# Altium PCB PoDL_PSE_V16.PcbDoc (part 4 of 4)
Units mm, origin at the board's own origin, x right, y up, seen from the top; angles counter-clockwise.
Board outline 155 x 86.5 mm, 4 copper layers (Top Layer, Signal Layer 2, Signal Layer 3, Bottom Layer), stack 1.586 mm thick; 431 components, 281 nets, 1286 pads, 864 vias.
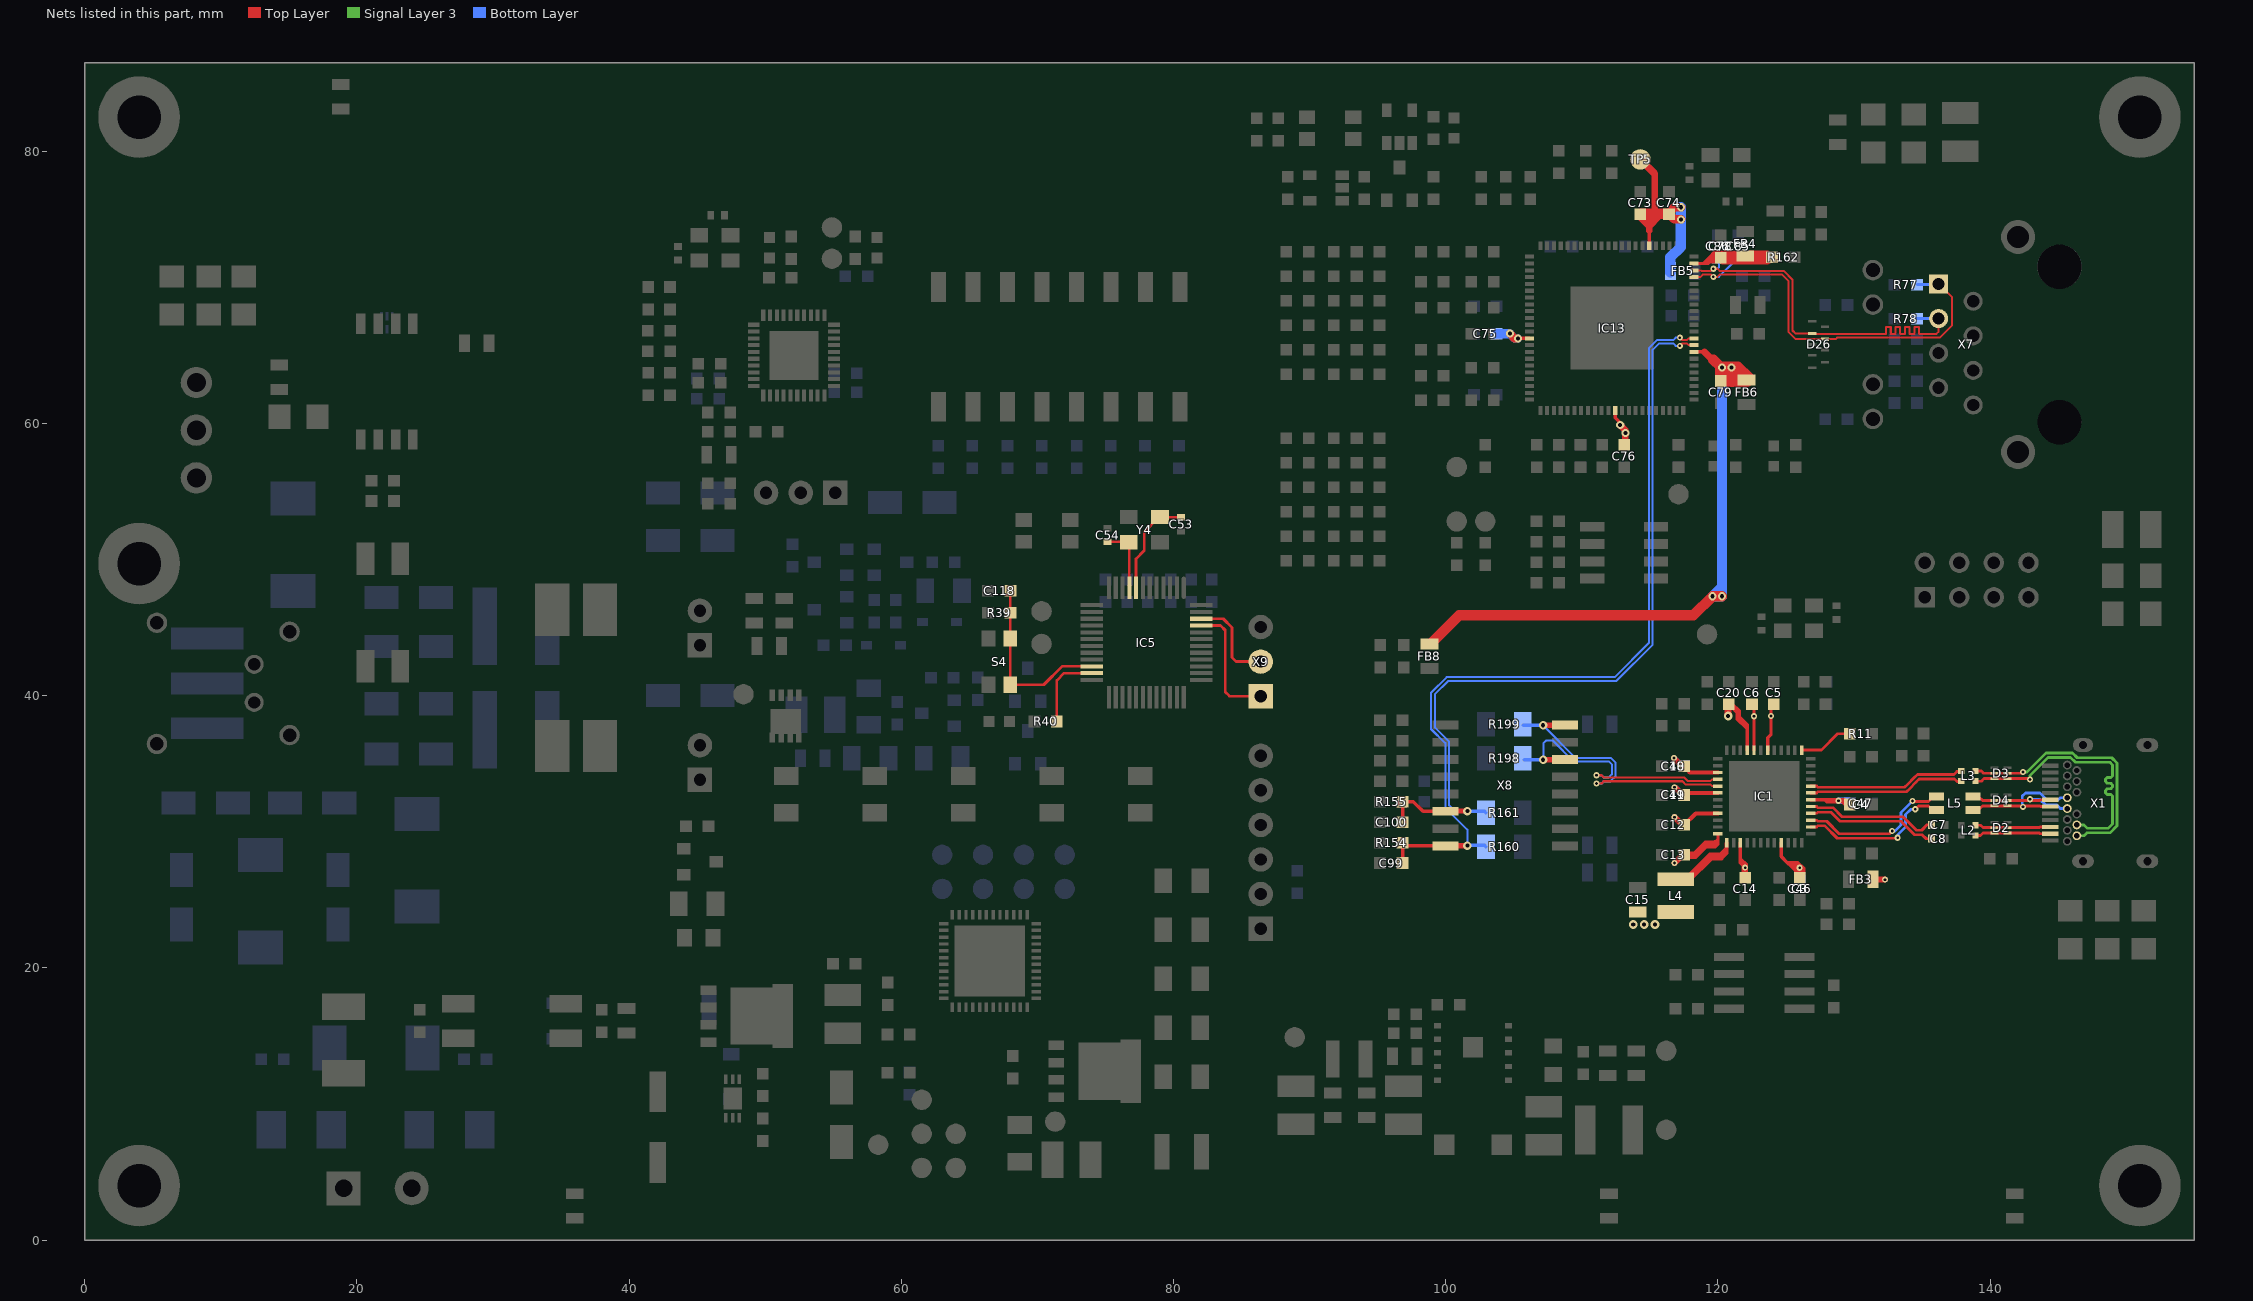
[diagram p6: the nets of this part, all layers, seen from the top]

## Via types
v1: diameter 0.6, hole 0.3, Top Layer to Bottom Layer, tented both sides, 494 vias
v2: diameter 0.45, hole 0.2, Top Layer to Bottom Layer, tented both sides, 173 vias
v3: diameter 0.635, hole 0.3, Top Layer to Bottom Layer, tented both sides, 145 vias
v4: diameter 1.016, hole 0.508, Top Layer to Bottom Layer, 40 vias
v5: diameter 1.016, hole 0.457, Top Layer to Bottom Layer, tented both sides, 8 vias
v6: diameter 0.762, hole 0.381, Top Layer to Bottom Layer, tented both sides, 4 vias

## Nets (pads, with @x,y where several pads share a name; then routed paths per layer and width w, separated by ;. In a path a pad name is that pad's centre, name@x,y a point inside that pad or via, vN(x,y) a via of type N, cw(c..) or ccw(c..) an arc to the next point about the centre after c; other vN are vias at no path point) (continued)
TR1_N: IC1.5 R199.1 X8.8 | length 21.3
  Top Layer w0.154: v2(111.079,33.546) 111.44,33.546 111.6,33.706 117.397,33.706 117.643,33.46 119.463,33.46 119.573,33.35 IC1.5@120,33.35
  Top Layer w0.381: v3(107.159,37.826) X8.8@108.741,37.826
  Bottom Layer w0.154: v3@107.143,37.81 109.522,35.431 112.117,35.431 112.481,35.066 112.481,34.094 112.093,33.706 111.599,33.706 111.439,33.546 v2(111.079,33.546)
  Bottom Layer w0.254: R199.1@105.695,37.826 v3(107.159,37.826)
TR1_P: IC1.4 R198.1 X8.6 | length 21.2
  Top Layer w0.154: v2(111.079,34.146) 111.44,34.146 111.599,33.988 ; 111.6,33.986 117.514,33.986 117.76,33.74 119.463,33.74 119.573,33.85 IC1.4@120,33.85
  Top Layer w0.381: v3(107.159,35.286) X8.6@108.741,35.286
  Bottom Layer w0.154: v3@107.173,35.3 107.173,36.492 107.381,36.7 107.856,36.7 109.406,35.15 112.001,35.15 112.201,34.95 112.201,34.211 111.976,33.986 111.6,33.986 111.44,34.146 v2(111.079,34.146)
  Bottom Layer w0.254: R198.1@105.765,35.286 v3(107.159,35.286)
TXA_N: C100.1 IC13.75 R155.1 R161.2 X8.14 | length 62.3
  Top Layer w0.154: v2(117.2,65.7) 117.36,65.86 117.739,65.86 117.849,65.75 IC13.75@118.25,65.75
  Top Layer w0.254: C100.1@96.826,30.7 96.826,32.2 97.626,32.2 98.331,31.495 ; 98.331,31.495 X8.14@99.99,31.495 98.331,31.495
  Top Layer w0.381: X8.14@100.009,31.514 v3(101.591,31.514)
  Bottom Layer w0.154: v3@101.591,31.5 100.686,31.5 100.25,31.936 100.25,36.617 99.201,37.667 99.201,40.1 100.176,41.076 112.526,41.076 115.201,43.75 115.201,65.4 115.66,65.86 116.741,65.86 116.901,65.7 v2(117.2,65.7)
  Bottom Layer w0.254: v3@101.591,31.5 102.851,31.5 R161.2@102.95,31.4
TXA_P: C99.1 IC13.76 R154.1 R160.2 X8.16 | length 62.6
  Top Layer w0.154: v2(117.2,66.3) 117.36,66.14 117.739,66.14 117.849,66.25 IC13.76@118.25,66.25
  Top Layer w0.254: C99.1@96.826,27.7 R154.1@96.826,28.9 ; R154.1@96.881,28.955 X8.16@99.99,28.955
  Top Layer w0.381: X8.16@100.009,28.974 v3(101.591,28.974)
  Bottom Layer w0.154: v3@101.591,28.961 v3(101.591,28.974) 101.591,29 101.591,30.145 99.97,31.767 99.97,36.501 98.92,37.551 98.92,40.216 100.06,41.356 112.41,41.356 114.92,43.866 114.92,65.516 115.544,66.14 116.741,66.14 116.901,66.3 v2(117.2,66.3)
  Bottom Layer w0.254: v3@101.591,29 102.851,29 R160.2@102.95,28.9
TXB_N: C86.1 D26.2 IC13.86 R78.1 X7.P3 | length 29.8
  Top Layer w0.147: IC13.86@118.25,71.25 118.75,71.25 118.799,71.201 118.803,71.204 119.497,71.204 119.5,71.207 ; 120.119,71.207 120.123,71.204 124.834,71.204 125.474,70.564 125.474,66.826 125.7,66.6 D26.2@126.925,66.6 ; D26.2@126.925,66.584 132.174,66.584 132.348,66.584 132.348,67.084 132.695,67.084 132.695,66.584 133.043,66.584 133.043,67.084 133.39,67.084 133.39,66.584 133.737,66.584 133.737,67.084 134.085,67.084 134.085,66.584 134.432,66.584 134.432,67.084 134.779,67.084 134.779,66.584 134.953,66.584 136.046,66.584 136.21,66.748 X7.P3@136.21,67.705
  Top Layer w0.154: 119.5,71.207 v2(119.66,71.367) 119.96,71.367 120.119,71.207
  Bottom Layer w0.154: v2(119.66,71.367) 119.992,71.367 120.09,71.464 C86.1@120.09,71.975
  Bottom Layer w0.203: R78.1@134.625,67.705 X7.P3@136.21,67.705
TXB_P: C85.1 D26.8 IC13.85 R77.1 X7.P1 | length 31
  Top Layer w0.147: IC13.85@118.25,70.75 118.7,70.75 118.876,70.926 119.5,70.926 ; 120.119,70.93 124.72,70.93 125.2,70.45 125.2,66.712 125.712,66.2 D26.8@127.875,66.2 128.65,66.2 128.76,66.31 136.285,66.31 137.2,67.225 137.2,69.255 X7.P1@136.21,70.245
  Top Layer w0.154: 119.5,70.926 v2(119.66,70.767) 119.96,70.767 120.119,70.926
  Bottom Layer w0.154: v2(119.66,70.767) 120.067,70.767 121.2,71.9 C85.1@121.2,72.174
  Bottom Layer w0.203: R77.1@134.625,70.2 136.165,70.2 X7.P1@136.21,70.245
USART1_RX: IC5.46 X9.2 | length 7.1
  Top Layer w0.203: IC5.46@82.025,45.65 83.65,45.65 84.3,45 84.3,42.8 84.6,42.5 X9.2@86.5,42.5
USART1_TX: IC5.45 X9.1 | length 9.3
  Top Layer w0.203: IC5.45@82.025,45.15 83.45,45.15 83.8,44.8 83.8,40.26 84.1,39.96 X9.1@86.5,39.96
USB2D1_N: D4.2 D4.5 L5.4 X1.A7 X1.B7 | length 8.7
  Top Layer w0.206: L5.4@138.85,32.6 139.154,32.6 139.454,32.3 140.425,32.3 141.375,32.3 143.667,32.3 143.717,32.35 X1.A7@144.42,32.35
  Bottom Layer w0.206: v2(142.923,32.384) 143.646,32.384 144.053,31.978 144.879,31.978 145.156,31.7 X1.B7@145.67,31.7
USB2D1_P: D4.1 D4.6 L5.1 X1.A6 X1.B6 | length 10.2
  Top Layer w0.206: L5.1@138.85,31.6 139.14,31.6 139.44,31.9 143.667,31.9 143.717,31.85 X1.A6@144.42,31.85
  Bottom Layer w0.206: v2@142.36,31.825 142.36,32.613 142.589,32.841 143.66,32.841 144.18,32.321 144.994,32.321 145.173,32.5 X1.B6@145.67,32.5
  other v2: 142.415,31.825
USB2D_N: IC1.27 L5.3 | length 13.2
  Top Layer w0.206: IC1.27@126.8,30.85 127.253,30.85 127.336,30.766 127.989,30.766 128.9,29.855 132.6,29.855 v2(132.8,30.055) ; 135.466,32.221 L5.3@135.8,32.555 ; 135.466,32.221 134.3,32.221 135.466,32.221 ; 135.466,32.221 L5.3@135.8,32.555 ; L5.3@135.8,32.555 136.05,32.555 L5.3@135.8,32.555
  Bottom Layer w0.206: v2(132.8,30.055) 133.015,30.055 133.457,30.498 133.457,31.412 v2(134.3,32.255)
USB2D_P: IC1.26 L5.2 | length 13.2
  Top Layer w0.206: IC1.26@126.8,30.35 127.253,30.35 127.337,30.434 127.851,30.434 128.762,29.522 v2@133.2,29.522 ; 134.734,31.889 135.466,31.889 ; 134.734,31.889 v2(134.5,31.655) 134.734,31.889 ; 134.734,31.889 135.466,31.889 ; 135.466,31.889 L5.2@135.8,31.555 ; 135.466,31.889 L5.2@135.8,31.555 ; L5.2@135.8,31.555 136.05,31.555 L5.2@135.8,31.555
  Bottom Layer w0.206: v2(133.2,29.555) 133.2,29.77 133.79,30.36 133.79,31.255 134.19,31.655 v2(134.5,31.655)
USB3RX1_N: D3.2 D3.5 L3.4 X1.B11 | length 22.4
  Top Layer w0.206: 139.353,34.456 139.509,34.3 ; 139.353,34.456 139.025,34.456 139.353,34.456 ; 139.353,34.456 139.509,34.3 ; 139.509,34.3 142.324,34.3 139.509,34.3
  Signal Layer 3 w0.206: v2(142.415,34.391) 142.713,34.391 144.113,35.79 146.045,35.79 146.402,35.433 148.934,35.433 149.318,35.048 149.318,30.443 148.793,29.918 147.118,29.918 146.9,29.7 X1.B11@146.37,29.7
USB3RX1_P: D3.1 D3.6 L3.1 X1.B10 | length 23.7
  Top Layer w0.206: 139.353,33.706 139.547,33.9 ; 139.353,33.706 139.025,33.706 139.353,33.706 ; 139.353,33.706 139.547,33.9 ; 139.547,33.9 D3.1@141.375,33.9 ; 139.547,33.9 D3.1@141.375,33.9 ; D3.1@141.375,33.9 142.928,33.9 D3.1@141.375,33.9
  Signal Layer 3 w0.206: v2(142.923,33.832) 142.923,34.13 144.25,35.457 145.907,35.457 146.264,35.1 148.796,35.1 148.986,34.911 148.986,34.1 148.862,33.977 148.601,33.977 148.478,33.853 148.478,33.689 148.601,33.565 148.862,33.565 148.986,33.442 148.986,33.277 148.862,33.154 148.601,33.154 148.478,33.03 148.478,32.866 148.601,32.742 148.862,32.742 148.986,32.619 148.986,32.536 148.986,30.581 148.655,30.25 147.15,30.25 146.9,30.5 X1.B10@146.37,30.5
USB3RX_N: IC1.32 L3.3 | length 11.9
  Top Layer w0.206: IC1.32@126.8,33.35 127.253,33.35 127.336,33.266 133.711,33.266 133.925,33.48 134.425,33.98 134.656,34.211 137.347,34.211 137.572,34.436 L3.3@137.9,34.436 ; 137.547,34.436 L3.3@137.875,34.436
USB3RX_P: IC1.31 L3.2 | length 11.6
  Top Layer w0.206: IC1.31@126.8,32.85 127.253,32.85 127.337,32.934 133.849,32.934 134.063,33.147 134.563,33.647 134.793,33.878 137.38,33.878 137.572,33.686 L3.2@137.9,33.686
USB3TX1_N: D2.2 D2.5 L2.4 X1.A3 | length 5.5
  Top Layer w0.206: L2.4@138.97,30.475 139.298,30.475 139.473,30.3 140.37,30.3 141.32,30.3 143.612,30.3 143.662,30.35 X1.A3@144.365,30.35
USB3TX1_P: D2.1 D2.6 L2.1 X1.A2 | length 5.5
  Top Layer w0.206: L2.1@138.97,29.725 139.298,29.725 139.473,29.9 140.37,29.9 141.32,29.9 143.612,29.9 143.662,29.85 X1.A2@144.365,29.85
USB3TX_N: C7.2 IC1.29 | length 9.8
  Top Layer w0.206: IC1.29@126.8,31.85 127.253,31.85 127.336,31.766 128.439,31.766 129.105,31.1 133.599,31.1 134.589,30.11 134.972,30.11 135.372,30.51 C7.2@135.725,30.51
USB3TX_P: C8.2 IC1.28 | length 9.8
  Top Layer w0.206: IC1.28@126.8,31.35 127.253,31.35 127.336,31.434 128.301,31.434 128.967,30.767 133.461,30.767 134.451,29.777 135.005,29.777 135.302,29.48 C8.2@135.725,29.48
USBRBIAS: IC1.37 R11.1 | length 4
  Top Layer w0.203: IC1.37@126.15,36 127.595,36 128.8,37.205 R11.1@129.675,37.205
USER_LED: IC5.23 R40.1 | length 5.8
  Top Layer w0.203: R40.1@71.426,38.1 71.426,41.125 71.95,41.65 IC5.23@73.975,41.65
USER_SW: C118.1 IC5.22 R39.2 S4.1 S4.3 | length 13.3
  Top Layer w0.203: S4.3@68,40.8 S4.1@68,44.2 68,47.675 C118.1@68.026,47.7 ; S4.3@68.1,40.8 70.465,40.8 71.815,42.15 IC5.22@73.975,42.15
VDD12: C3.1 C4.1 C5.1 C6.1 C14.1 C15.2 C46.1 C47.1 FB3.2 IC1.15 IC1.21 IC1.30 IC1.42 IC1.44 L4.2 | length 24.5
  Top Layer w0.25: IC1.15@121.65,29.2 121.65,28.021 ; C14.1@121.995,26.561 121.868,26.688 121.868,27.513 121.65,27.731 121.65,28.021 ; C14.1@122.1,26.666 122.1,27.361 122.1,27.571 121.65,28.021 ; IC1.44@122.65,36 C6.1@122.65,39.23 ; IC1.42@123.65,36 123.65,36.905 123.9,37.155 C5.1@123.9,38.98 ; IC1.21@124.65,29.2 124.65,28.181 125.1,27.731 ; C3.1@125.7,26.688 125.7,27.131 125.413,27.418 125.1,27.731 ; C3.1@126,26.581 126.3,26.881 126.3,27.307 125.876,27.731 125.55,27.731 125.1,27.731 ; IC1.30@126.8,32.35 127.828,32.35 ; 127.828,32.35 128.853,32.35 129.33,32.35 129.7,31.98 129.345,31.98 129.125,32.2 128.853,32.2 127.978,32.2 127.828,32.35
  Top Layer w0.45: FB3.2@131.4,26.48 v2(132.274,26.48)
  Top Layer w0.508: 125.55,27.555 125.837,27.268 126,27.105 C3.1@126,26.581
  Bottom Layer w0.45: v2(128.853,32.28) C47.1@129.627,32.28
  Bottom Layer w0.508: C46.1@126,26.581 v2(126,27.355)
  other v2: 121.995,27.361 122.655,38.485 123.9,38.5
  other v3: 113.775,23.18 114.575,23.18 115.375,23.18
VDD12_SW_OUT: IC1.13 L4.1 | length 12.7
  Top Layer w0.25: L4.1@117.477,26.427 119.405,28.355 120.18,28.355 120.6,28.775 IC1.13@120.6,29.155 ; L4.1@117.672,26.427 119.4,28.155 120.25,28.155 120.575,28.48 120.65,28.555 ; L4.1@117.936,26.427 119.53,28.021 120.266,28.021 120.325,28.08 120.65,28.405 120.65,28.555 ; IC1.13@120.65,29.2 120.65,28.775 120.65,28.555
VDD25: C10.1 C11.1 C12.1 C13.1 C20.1 C48.1 C49.1 IC1.3 IC1.6 IC1.9 IC1.12 IC1.45 | length 29.5
  Top Layer w0.2: C13.1@117.5,28.28 C13.1@117.606,28.175 ; C13.1@117.606,28.1 118.38,28.1 119.13,28.85 119.77,28.85 120,29.08 120,29.48 ; C13.1@117.67,28.45 118.245,28.45 119.045,29.25 119.77,29.25 120,29.48 ; IC1.12@120,29.85 120,29.48
  Top Layer w0.25: C13.1@117.5,28.28 118.335,28.28 119.087,29.032 119.675,29.032 119.77,29.127 119.77,29.25 ; C20.1@120.884,39.304 121.4,38.788 121.4,38.305 122.15,37.555 ; C20.1@121.051,39.379 121.55,38.88 121.55,38.455 122.15,37.855 122.15,37.555 ; IC1.45@122.15,36 122.15,37.555
  Top Layer w0.305: C12.1@117.5,30.48 118.37,31.35 IC1.9@120,31.35 ; C11.1@117.5,32.68 117.67,32.85 IC1.6@120,32.85 ; C10.1@117.5,34.78 117.931,34.35 IC1.3@120,34.35
  Top Layer w0.45: v2(116.763,35.412) C10.1@117.345,34.83 ; v2(116.8,27.7) C13.1@117.382,28.282 ; v2(116.813,31.062) C12.1@117.395,30.48 ; v2(116.813,33.262) C11.1@117.395,32.68 ; C13.1@117.5,28.28 C13.1@117.67,28.45
  Top Layer w0.508: v3(120.75,38.505) C20.1@120.75,39.28
  Bottom Layer w0.45: v2(116.763,35.412) C48.1@117.375,34.8 ; v2(116.813,33.262) C49.1@117.425,32.65
VDD33TXRX1: C79.1 FB6.2 FB8.2 IC13.74 | length 51.8
  Top Layer w0.254: IC13.74@118.25,65.25 119.012,65.25
  Top Layer w0.508: 119.012,65.25 119.572,64.69
  Top Layer w0.762: FB8.2@98.901,43.8 101.001,45.9 118.201,45.9 v1(119.6,47.3) v1(120.301,47.3) ; 119.647,64.69 v1@120.155,64.182 ; C79.1@120.155,63.166 120.155,63.8 ; 121.125,63.2 121.125,63.212 ; 121.468,63.8 120.155,63.8 ; FB6.2@122.25,63.4 121.468,64.182 v1@120.155,64.182 ; 120.155,63.8 v1@120.155,64.182
  Top Layer w1.016: C79.1@120.3,63.2 121.125,63.2 122,63.2 FB6.2@122.1,63.2
  Bottom Layer w0.762: 120.301,48 v1(120.301,47.3) v1(119.6,47.3) 120.301,48 ; 120.301,48 120.301,63.5 ; 120.3,63.5 v1(120.3,64.1) v1(121,64.1) 120.4,63.5 120.3,63.5
VDD33TXRX2: C78.1 FB4.2 IC13.87 R162.1 | length 9.5
  Top Layer w0.254: IC13.87@118.25,71.75 118.944,71.75 ; 119.758,72.564 118.944,71.75 ; C78.1@119.875,71.875 119.386,71.875 ; C78.1@120.2,72.175 119.686,72.175 119.386,71.875 ; 118.944,71.75 119.262,71.75 119.386,71.875
  Top Layer w0.762: C78.1@119.85,72.325 FB4.2@122.45,72.325
  Top Layer w1.016: C78.1@120.409,72.183 R162.1@123.557,72.183
VDDCR: C73.2 C74.1 C75.1 C76.1 FB5.2 IC13.6 IC13.35 IC13.56 TP5.1 | length 22.5
  Top Layer w0.254: v1@105.248,66.25 v1(105.3,66.25) IC13.35@106.15,66.25 ; IC13.56@112.45,60.95 112.45,60.422 112.74,60.132 v1@112.74,60.094 ; IC13.6@114.95,73.05 114.95,74.188
  Top Layer w0.508: v1(112.816,59.891) 113.185,59.522 C76.1@113.185,58.707 ; TP5.1@114.3,79.4 115.356,78.344 115.356,75.331 ; 114.95,74.188 114.95,74.671 114.95,75.179
  Top Layer w0.6: v1(104.715,66.595) 105.06,66.25 v1@105.248,66.25
  Top Layer w0.635: C74.1@116.4,75.375 116.781,74.994 v1(117.289,74.994) ; C74.1@116.4,75.502 116.781,75.883 v1(117.289,75.883)
  Top Layer w0.762: C73.2@114.368,75.4 115.003,75.4 ; C73.2@114.417,75.204 114.95,74.671 115.483,75.204 ; 115.511,75.4 C74.1@116.4,75.4
  Bottom Layer w0.6: v1(104.715,66.595) 105.059,66.25 v1(105.3,66.25)
  Bottom Layer w0.7: C75.1@103.731,66.595 v1(104.715,66.595)
  Bottom Layer w0.762: FB5.2@116.499,71.1 116.499,72.199 117.261,72.961 v1@117.261,75.883
  other v1: 113.2,59.3
XT1: C53.2 IC5.8 Y4.1 | length 7.3
  Top Layer w0.203: IC5.8@77.25,47.925 77.25,50.05 77.85,50.65 77.85,52.025 Y4.1@78.825,53 ; Y4.1@79,53.125 79.025,53.1 C53.2@80.55,53.1
XT2: C54.2 IC5.9 Y4.3 | length 4.9
  Top Layer w0.203: C54.2@75.15,51.3 76.675,51.3 Y4.3@76.7,51.275 ; IC5.9@76.75,47.925 Y4.3@76.75,51.275
pads on no net: D2.4 D3.4 D4.4 D17.4 D19.2 D26.1 D26.5 D26.6 D26.9 IC1.7 IC1.8 IC1.10 IC1.11 IC2.8 IC2.11 IC3.7 IC4.5 IC4.14 IC4.15 IC5.1 IC5.2 IC5.3 IC5.11 IC5.15 IC5.16 IC5.17 IC5.18 IC5.21 IC5.28 IC5.29 IC5.30 IC5.31 IC5.32 IC5.33 IC5.34 IC5.37 IC5.38 IC5.39 IC5.40 IC5.41 IC5.42 IC5.43 IC5.44 IC5.47 IC9.10 IC9.11 IC9.18 IC9.21 IC10.1 IC11.1 IC13.3 IC13.11 IC13.18 IC13.29 IC13.31 IC13.45 IC13.67 IC13.68 IC13.88 X1.A4 X1.A8 X1.A9 X1.A10 X1.A11 X1.B2 X1.B3 X1.B4 X1.B5 X1.B8 X1.B9 X7.H1 X7.H2 X7.P7 X8.4 X8.5 X8.12 X8.13

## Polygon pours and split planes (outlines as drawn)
+3V3 on Top Layer "Top Layer-+3V3" (solid, remove dead copper, pour order 199): 113,5.5 113,10.5 112.8,10.7 109.8,10.7 109.6,10.9 109.6,12.6 109.7,12.7 117.15,12.7 117.382,12.468 117.382,5.508 117.074,5.2 113.274,5.2 113,5.475
NetC124_1 on Top Layer "Top Layer-NetC124_1" (solid, remove dead copper, pour order 197): 99,5.475 99.275,5.2 110.7,5.2 111,5.5 111,10 110.9,10.1 109.441,10.1 109.3,9.959 109.3,8.3 108.8,7.8 99.2,7.8 99,7.6
NetC26_1 on Top Layer "Top Layer-NetC26_1" (solid, remove dead copper, pour order 196): 93.5,10.3 99.6,10.3 99.7,10.4 99.7,12.935 99.6,13.035 99.135,13.035 99,12.9 98.4,12.3 95.1,12.3 94.8,12.6 94.8,14.7 94.625,14.875 93.669,14.875 93.6,14.806 93.6,11.939 93.4,11.739 93.4,10.4
+24V on Top Layer "Top Layer-+24V" (solid, remove dead copper, pour order 194): 92.5,11.634 92.2,11.934 92.2,15.6 92,15.8 87.5,15.8 87.3,15.6 87.3,10.4 87.4,10.3 92.4,10.3 92.5,10.4
GND on Top Layer "Top Layer-GND 2" (solid, remove dead copper, pour order 164): 34.1,14.226 34.1,3.1 34.5,2.7 52.4,2.7 52.7,3 52.7,7.175 52.175,7.7 41.174,7.7 40.4,8.475 40.4,14.3 40.2,14.5 34.375,14.5
no net on Top Layer "Top Layer-No Net" (solid, remove dead copper, pour order 162): 48.1,9
+VPSE on Top Layer "Top Layer-+VPSE" (solid, remove dead copper, pour order 160): 46.8,29.1 46.125,29.1 45.9,28.875 45.9,26.575 46.1,26.375 47.087,26.375 47.5,25.962 47.5,13.45 48,12.95 48,11.45 48.939,11.45 49.189,11.7 51.275,11.7 51.6,11.375 51.6,10.226 51.925,9.9 57.181,9.9 57.431,10.15 57.431,12.769 57.1,13.1 53.3,13.1 53,13.4 53,16.626 53.3,16.9 57.3,16.9 57.45,17.05 57.45,19.165 57.215,19.4 55.85,19.4 55.5,19.75 55.5,21.875 55.925,22.3 58,22.3 58,23.3 52.8,28.5 52.8,32.05 49.75,32.05
no net on Top Layer "Top Layer-No Net 1" (solid, remove dead copper, pour order 158): 47.456,14.051
+24V on Top Layer "+24V_FILTER" (solid, remove dead copper, pour order 156): 44.95,15.35 44.7,15.1 44.7,13.735 46.235,12.2 47.2,12.2 47.2,11.5 46.6,11.5 46.5,11.4 46.5,9.4 46.6,9.3 47.7,9.3 47.7,8.6 45.4,8.6 44.9,9.1 41.3,9.1 40.9,9.5 40.9,16.308 40.708,16.5 34.2,16.5 34.1,16.6 34.1,19.2 34.49,19.59 46.2,19.59 46.625,19.165 46.625,15.5 46.476,15.35
+24V_IN on Top Layer "Top Layer-+24V_IN 1" (solid, remove dead copper, pour order 154): 28.6,16.6 28.4,16.4 22.2,16.4 20.8,15 17,15 16.7,15.3 16.7,18.877 17,19.177 28.323,19.177 28.6,18.9
NetC97_2 on Top Layer "Top Layer-NetC97_2" (solid, remove dead copper, pour order 152): 28.1,2.5 22.3,2.5 21.9,2.9 21.9,14.9 22.7,15.7 28.4,15.7 28.6,15.5 28.6,3
NetF1_1 on Top Layer "Top Layer-NetF1_1" (solid, remove dead copper, pour order 150): 20.8,2.5 17.1,2.5 16.7,2.9 16.7,13.7 17.1,14.1 20.8,14.1 21.2,13.7 21.2,2.9
no net on Top Layer "Top Layer-No Net 2" (solid, remove dead copper, pour order 144): 43.55,32.326
NetIC4_3 on Top Layer "Top Layer-NetIC4_3" (solid, remove dead copper, pour order 142): 52.7,33.4 50,33.4 49.775,33.625 49.775,38.815 49.96,39 52.8,39 52.9,38.9 52.9,33.6
NetC111_2 on Top Layer "Top Layer-NetC111_2" (solid, remove dead copper, pour order 140): 49.85,42.3 43.75,42.3 43.55,42.5 43.55,44.715 43.735,44.9 47.4,44.9 47.6,45.1 47.6,45.8 47.8,46 49.86,46 50.06,45.8 50.06,42.535 49.825,42.3
OUTP0 on Top Layer "Top Layer-OUTP0" (solid, remove dead copper, pour order 138): 51,40.9 50.6,41.3 50.6,45.75 50.75,45.9 52.7,45.9 52.9,45.7 52.9,39.6 51.075,39.6 51,39.675
LSNS on Top Layer "Top Layer-LSNS" (solid, remove dead copper, pour order 132): 79.9,27.112 79.9,2.5 79.5,2.1 53.8,2.1 53.5,2.4 53.5,8.6 53.9,9 58.7,9 59.1,8.6 59.1,4.725 59.825,4 72.5,4 73,4.5 73,15.45 75.6,18.05 75.6,26.712 76,27.112
GND on Top Layer "Top Layer-GND 1" (solid, remove dead copper, pour order 128): 69.846,11.5 69.846,14.251 69.165,14.932 69.165,16.483 71.718,16.483 71.925,16.275 71.925,11.5
GND on Top Layer "Top Layer-GND" (solid, remove dead copper, pour order 96): 56.8,45.014 55.414,46.4 47.8,46.4 47.6,46.6 47.6,50.25 46.75,51.1 41.2,51.1 40.4,51.9 40.4,60.181 35.928,64.654 17.946,64.654 17.3,65.3 17.3,67.2 14.6,69.9 5.2,69.9 4.7,70.4 4.7,77.925 10.675,83.9 27.1,83.9 125,83.9 127.95,80.95 139.075,80.95 139.7,80.275 139.7,55.617 140.517,54.8 149.4,54.8 149.8,54.4 149.8,39.6 152.4,37 152.4,23.9 151.9,23.4 144.2,23.4 143.2,22.4 143.2,3.4 142.5,2.7 81.3,2.7 80.9,3.1 80.9,8.4 81.2,8.7 84.631,8.7 85.631,9.7 85.631,36.715 85.06,37.286 81.086,37.286 79.8,36 57.256,36 56.8,36.456
SHIELD on Top Layer "Top Layer-SHIELD" (solid, remove dead copper, pour order 92): 13.1,68.9 4.6,68.9 3.8,69.7 3.8,79 9.3,84.5 14.7,84.5 125.396,84.5 128.196,81.7 139.612,81.7 140.823,80.489 140.823,56.2 141.323,55.7 150,55.7 150.9,54.8 150.9,40.03 153.3,37.63 153.3,23.1 152.5,22.3 144.6,22.3 143.985,21.685 143.985,2.485 143.5,2 80.6,2 80.1,1.5 53.2,1.5 52.7,2 34,2 34,0 53,0 155,0 155,86.5 0,86.5 0,0 31.5,0 31.5,2 30,2 29.5,1.5 15.1,1.5 14.6,2 9.4,2 3.8,7.6 3.8,34.85 4.236,35.286 15.086,35.286 15.6,35.8 15.6,37.65 7.15,37.65 6.6,38.2 6.6,44 7,44.4 15.6,44.4 15.6,46.246 15.146,46.7 8.45,46.7 7.9,47.25 7.9,52.4 7.199,53.101 5.802,53.098 5.2,53.7 5.2,61.5 5.7,62 9.9,62 11.3,63.4 15.2,63.4 15.6,63.8 15.6,66.4
GND on Top Layer "GND_OSC" (solid, remove dead copper, pour order 76): 122.475,43.303 122.175,43.603 122.175,48.003 122.475,48.303 129.345,48.303 129.669,47.979 129.669,43.548 129.425,43.303
+3V3 on Top Layer "+3V3_L01_P074" (hatched Horizontal grid 0.203 track 0.203, remove dead copper, pour order 74): 118.92,38.47 118.92,39.05 119.38,39.05 119.45,38.98 119.45,38.655 120.3,37.805 121.3,37.805 121.65,37.455 121.65,36.788 121.133,37.305 120.085,37.305
+3V3 on Top Layer "+3V3_L01_P072" (hatched Horizontal grid 0.203 track 0.203, remove dead copper, pour order 72): 126,38.305 125.15,37.455 125.15,37.105 125.595,37.55 126.445,37.55 126.6,37.705 126.6,38.98 126.338,39.242 126,39.242
+3V3 on Top Layer "+3V3_L01_P070" (hatched Horizontal grid 0.203 track 0.203, remove dead copper, pour order 70): 127.6,37.805 127.6,39.08 128.2,39.08 128.2,37.605 127.576,36.981 127,36.981 127,37.205
GND on Bottom Layer "Top Layer-GND" (solid, remove dead copper, pour order 190): 17.3,67.2 14.6,69.9 5.2,69.9 4.7,70.4 4.7,77.925 10.675,83.9 17.581,83.9 27.1,83.9 125,83.9 127.95,80.95 139.075,80.95 139.7,80.275 139.7,55.617 140.517,54.8 149.4,54.8 149.8,54.4 149.8,39.6 152.4,37 152.4,23.803 151.997,23.4 144.2,23.4 143.2,22.4 143.2,3.4 142.5,2.7 81.3,2.7 34.5,2.7 34.1,3.1 34.1,19.2 34.49,19.59 40.044,19.59 40.5,20.046 40.5,60.082 35.928,64.654 17.946,64.654 17.3,65.3
SHIELD on Bottom Layer "Top Layer-SHIELD" (solid, remove dead copper, pour order 178): 15.6,66.415 15.6,62.6 16.6,61.6 16.6,54.4 14,54.4 14,60.3 12.3,62 9.9,62 5.7,62 5.2,61.5 5.2,53.7 5.802,53.098 7.194,53.098 7.9,52.4 7.9,47.6 5.3,45 5.3,44.6 5.3,37.2 5.8,36.7 5.8,35.286 4.236,35.286 3.8,34.85 3.8,7.6 9.4,2 14,2 14.5,1.5 29.5,1.5 30,2 31.5,2 31.5,0 0,0 0,86.5 155,86.5 155,0 53,0 34,0 34,2 52.7,2 53.2,1.5 80.1,1.5 80.6,2 143.5,2 143.985,2.485 143.985,21.685 144.6,22.3 152.5,22.3 153.3,23.1 153.3,37.63 150.9,40.03 150.9,54.8 150,55.7 141.323,55.7 140.823,56.2 140.823,80.489 139.612,81.7 128.196,81.7 125.396,84.5 14.7,84.5 9.3,84.5 3.8,79 3.8,69.7 4.6,68.9 13.115,68.9
+VPSE on Bottom Layer "Bottom Layer-+VPSE" (solid, remove dead copper, pour order 168): 47.463,15.438 47.463,29.813 49.7,32.05 52.8,32.05 52.8,15.5 52.6,15.3 47.6,15.3
+24V on Bottom Layer "Bottom Layer-+24V" (solid, remove dead copper, pour order 166): 46.625,15.5 46.476,15.35 43.175,15.35 43.025,15.5 43.025,19.416 43.2,19.59 46.2,19.59 46.625,19.165
OUTP0 on Bottom Layer "Bottom Layer-OUTP0" (solid, remove dead copper, pour order 148): 50.3,34.8 50.3,37.75 49.9,38.15 45.25,38.15 44.9,38.5 44.9,41.4 45.2,41.7 49.9,41.7 50.3,42.1 50.3,50.2 50.5,50.4 54.1,50.4 54.3,50.2 54.3,45.6 53.225,44.525 53.225,34.825 53,34.6 50.5,34.6
OUTM0 on Bottom Layer "Bottom Layer-OUTM0" (solid, remove dead copper, pour order 136): 43.8,32.3 47.1,32.3 47.7,32.9 68.738,32.9 69.1,33.262 69.1,35.367 68.8,35.667 66.212,35.667 66,35.455 66,34.2 65.8,34 62.9,34 62.7,34.2 62.7,36.356 62.5,36.556 58.431,36.556 58.2,36.325 58.2,34.2 58,34 49.7,34 48.7,35 43.7,35 43.5,34.8 43.5,32.6
LSNS on Bottom Layer "Top Layer-LSNS" (solid, remove dead copper, pour order 134): 53.694,4.006 53.494,3.806 53.494,2.406 53.894,2.006 79.494,2.006 79.894,2.406 79.894,27.118 77.024,27.118 76.6,26.694 76.6,19.062 72.994,15.456 72.994,4.506 72.494,4.006
NetD12_2 on Bottom Layer "Bottom Layer-NetD12_2" (solid, remove dead copper, pour order 84): 5.2,24.5 5.7,25 19.9,25 20.3,24.6 20.3,20 19.8,19.5 5.7,19.5 5.2,20
NetD11_1 on Bottom Layer "Bottom Layer-NetD11_1" (solid, remove dead copper, pour order 82): 9.2,33.2 9.2,26.4 9.5,26.1 16,26.1 16.5,26.6 16.5,33.4 16.3,33.6 9.6,33.6
GND on Signal Layer 2 "Top Layer-GND" (solid, remove dead copper, pour order 184): 17.3,67.2 14.6,69.9 5.2,69.9 4.7,70.4 4.7,77.925 10.675,83.9 17.6,83.9 27.1,83.9 125,83.9 127.95,80.95 139.075,80.95 139.7,80.275 139.7,55.617 140.517,54.8 149.4,54.8 149.8,54.4 149.8,39.6 152.4,37 152.4,23.803 151.997,23.4 144.2,23.4 143.2,22.4 143.2,3.4 142.5,2.7 81.3,2.7 34.5,2.7 34.1,3.1 34.1,19.2 34.49,19.59 40.044,19.59 40.5,20.046 40.5,60.082 35.928,64.654 17.946,64.654 17.3,65.3
SHIELD on Signal Layer 2 "Top Layer-SHIELD" (solid, remove dead copper, pour order 180): 13.5,68.5 13.1,68.9 4.6,68.9 3.8,69.7 3.8,79 9.3,84.5 14.7,84.5 125.396,84.5 128.196,81.7 139.612,81.7 140.823,80.489 140.823,56.2 141.323,55.7 150,55.7 150.9,54.8 150.9,40.03 153.3,37.63 153.3,23.1 152.5,22.3 144.6,22.3 143.985,21.685 143.985,2.485 143.5,2 80.6,2 80.1,1.5 53.2,1.5 52.7,2 34,2 34,0 53,0 155,0 155,86.5 0,86.5 0,0 31.5,0 31.5,2 30,2 29.5,1.5 15.1,1.5 14.6,2 9.4,2 3.8,7.6 3.8,34.85 4.236,35.286 15.086,35.286 15.6,35.8 15.6,37.283 15.233,37.65 7.15,37.65 6.6,38.2 6.6,44 7,44.4 15.178,44.4 15.6,44.822 15.6,46.246 15.146,46.7 8.45,46.7 7.9,47.25 7.9,52.4 7.202,53.098 5.802,53.098 5.2,53.7 5.2,61.5 5.7,62 9.9,62 11.3,63.4 15.2,63.4 15.6,63.8 15.6,66.4
GND on Signal Layer 3 "Top Layer-GND" (solid, remove dead copper, pour order 188): 17.3,67.2 14.6,69.9 5.2,69.9 4.7,70.4 4.7,77.925 10.675,83.9 17.6,83.9 27.1,83.9 125,83.9 127.95,80.95 139.075,80.95 139.7,80.275 139.7,55.617 140.517,54.8 149.4,54.8 149.8,54.4 149.8,39.6 152.4,37 152.4,23.803 151.997,23.4 144.2,23.4 143.2,22.4 143.2,3.4 142.5,2.7 81.3,2.7 34.5,2.7 34.1,3.1 34.1,19.2 34.49,19.59 40.044,19.59 40.5,20.046 40.5,60.082 35.928,64.654 17.946,64.654 17.3,65.3
SHIELD on Signal Layer 3 "Top Layer-SHIELD" (solid, remove dead copper, pour order 182): 13.1,68.9 4.6,68.9 3.8,69.7 3.8,79 9.3,84.5 14.7,84.5 125.396,84.5 128.196,81.7 139.612,81.7 140.823,80.489 140.823,56.2 141.323,55.7 150,55.7 150.9,54.8 150.9,40.03 153.3,37.63 153.3,23.1 152.5,22.3 144.6,22.3 143.985,21.685 143.985,2.485 143.5,2 80.6,2 80.1,1.5 53.2,1.5 52.7,2 34,2 34,0 53,0 155,0 155,86.5 0,86.5 0,0 31.5,0 31.5,2 30,2 29.5,1.5 15.1,1.5 14.6,2 9.4,2 3.8,7.6 3.8,34.85 4.236,35.286 15.086,35.286 15.6,35.8 15.6,37.3 15.25,37.65 7.15,37.65 6.6,38.2 6.6,44 7,44.4 15.3,44.4 15.6,44.7 15.6,46.246 15.146,46.7 8.45,46.7 7.9,47.25 7.9,49.9 5.2,52.6 5.2,61.5 5.7,62 9.9,62 11.3,63.4 15.2,63.4 15.6,63.8 15.6,66.4
+VPSE on Signal Layer 3 "Signal Layer 3-+VPSE" (solid, remove dead copper, pour order 174): 78.656,32.05 78.9,31.806 78.9,29.854 78.746,29.7 54.648,29.7 52.8,27.756 52.8,13.8 52.525,13.525 47.746,13.525 47.463,13.809 47.463,29.813 49.7,32.05
+24V on Signal Layer 3 "Signal Layer 3-+24V" (solid, remove dead copper, pour order 170): 87.4,7 88,7.6 88,13.689 88.274,13.964 89.687,13.964 89.9,13.75 89.9,6.286 88.914,5.3 43.8,5.3 43.025,6.074 43.025,15.5 43.025,19.225 43.39,19.59 46.2,19.59 46.625,19.165 46.625,7.575 47.2,7
OUTM0 on Signal Layer 3 "Signal Layer 3-OUTM0" (solid, remove dead copper, pour order 146): 43.5,32.6 43.8,32.3 47.1,32.3 47.6,32.8 82.7,32.8 82.9,33 82.9,35.4 82.694,35.606 47.444,35.606 46.838,35 43.7,35 43.5,34.8 43.5,32.5
VDD12 on Signal Layer 3 "Signal Layer 3-VDD12" (solid, remove dead copper, pour order 118): 113.4,22.7 118.738,22.7 119.4,23.362 119.4,26.8 119.6,27 122.747,27 122.9,27.153 122.9,27.637 123.093,27.83 125.265,27.83 125.395,27.7 125.395,26.405 125.6,26.2 132.4,26.2 132.55,26.35 132.55,26.95 132.347,27.153 129.747,27.153 129.4,27.5 129.4,38.1 128.6,38.9 122.4,38.9 122.212,38.712 122.212,38.083 122.395,37.9 127.953,37.9 128.3,37.553 128.3,29.1 128,28.8 119.02,28.8 118.2,27.98 118.2,24.1 118,23.9 113.5,23.9 113.3,23.7 113.3,22.8
VDD25 on Signal Layer 3 "Signal Layer 3-VDD25" (solid, remove dead copper, pour order 116): 116.1,27.5 116.3,27.3 117.2,27.3 117.4,27.5 117.4,37.7 117.826,38.126 121.048,38.126 121.229,38.307 121.229,39.191 121.019,39.4 117,39.4 116.1,38.5
VDDCR on Signal Layer 3 "Signal Layer 3-VDDCR" (solid, remove dead copper, pour order 114): 112.8,58.9 112.5,59.2 112.5,62.6 112.1,63 104.55,63 104.3,63.25 104.3,66.9 104.5,67.1 108.3,67.1 108.5,67.3 108.5,71.215 108.8,71.515 116.515,71.515 116.8,71.8 116.8,76.1 117.1,76.4 118.3,76.4 118.5,76.2 118.5,61.3 118.2,61 116.3,61 116.1,60.8 116.1,59.121 115.879,58.9
+3V3 on Signal Layer 3 "Signal Layer 3-+3V3" (solid, remove dead copper, pour order 110): 136.4,46.3 133.9,43.8 133.9,24.6 133.9,7.948 132.602,6.65 99.85,6.65 99.229,7.271 99.229,18.226 99.229,23.571 98.6,24.2 90.9,24.2 88.75,22.05 84.6,22.05 84.2,22.45 84.2,25.152 84.2,40.354 83.554,41 58.914,41 58.2,41.714 58.2,55.933 57.633,56.5 44.4,56.5 43.9,57 43.9,70.9 44.6,71.6 83.6,71.6 85.4,73.4 85.4,82.7 86.1,83.4 124.7,83.4 127.5,80.6 127.5,59.2 136.4,50.3

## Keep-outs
Keep-Out Layer:
  the board outline again, w0.2

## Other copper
Top Layer:
  rectangle net GND: 47.8,46.4 52.503,48.88
  rectangle net +3V3: 109.6,11.1 113.6,12.7
  rectangle net +3V3: 113,5.9 115,12.7
  rectangle net GND: 53.5,14.4 55.5,16
  rectangle net SHIELD: 30.35,0.4 35.35,2
  rectangle net GND: 34.1,13.7 40.4,15.7
  rectangle net NetC122_2: 48,8.6 50.8,11.2
  rectangle net +VPSE: 47.7,13.5 52.431,19.8
  rectangle net NetC38_2: 67.8,4.6 71.9,6.9
  rectangle net +VPSE: 75.7,29.8 78.8,32.05
  rectangle net +VPSE: 69.2,29.8 72.3,32.05
  rectangle net +VPSE: 49.7,29.8 52.8,32.05
  rectangle net +VPSE: 56.2,29.8 59.3,32.05
  rectangle net +VPSE: 62.7,29.8 65.8,32.05
  region net GND: 69.846,16.275 69.846,11.5 71.925,11.5 71.925,16.275
  rectangle net NetC57_1: 46.7,64.25 49.15,64.8
  rectangle net GND: 122.45,45.546 123.75,46.8
  rectangle net GND: 123.565,45.92 125.811,47.6
  region net GND: 128.481,45.7 126.5,45.7 126.5,43.825 128.481,43.825
  region net GND: 129.45,45.854 128.15,45.854 128.15,44.6 129.45,44.6
  rectangle net VDD12: 113.275,22.58 118.38,24.48
  pour cut-out: 111,6.3 111,9.9 111.118,10.018 112.882,10.018 113,9.9 113,6.3 112.9,6.2 111.1,6.2
  pour cut-out: 92.2,11.934 92.2,14.64 92.26,14.7 93.54,14.7 93.6,14.64 93.6,11.939 93.561,11.9 92.234,11.9
  region: 4.8,40.8
  region: 59.175,72.15
  region net +3V3: 49.3,70.7
  region: 74.3,58.5
  pour cut-out: 125.05,43.28 122.55,43.28 122.2,43.63 122.2,48.03 122.5,48.33 129.37,48.33 129.695,48.006 129.695,43.575 129.4,43.28 125.495,43.28 125.495,43.057 129.538,43.057 129.919,43.438 129.919,48.137 129.513,48.544 122.375,48.544 121.994,48.163 121.994,43.438 122.375,43.057 125.05,43.057
  text "Top Layer" at 68.2,91.8 h1.8
Signal Layer 2:
  rectangle net SHIELD: 30.35,0.4 35.35,2
  pour cut-out: 111,6.3 111,9.9 111.118,10.018 112.882,10.018 113,9.9 113,6.3 112.9,6.2 111.1,6.2
  pour cut-out: 92.2,11.934 92.2,14.64 92.26,14.7 93.54,14.7 93.6,14.64 93.6,11.939 93.561,11.9 92.234,11.9
  text "Inner Layer2 (GND Plane)" at 56.2,91.7 h1.8
Signal Layer 3:
  rectangle net +3V3: 134.936,48.791 135.444,50.902
  rectangle net SHIELD: 30.35,0.4 35.35,2
  pour cut-out: 111,6.3 111,9.9 111.118,10.018 112.882,10.018 113,9.9 113,6.3 112.9,6.2 111.1,6.2
  pour cut-out: 92.2,11.934 92.2,14.64 92.26,14.7 93.54,14.7 93.6,14.64 93.6,11.939 93.561,11.9 92.234,11.9
  pour cut-out: 72.1,15.334 71.5,15.934 71.5,22 77.056,27.556 84,27.556 84,22.413 84,9.1 72.1,9.1
  pour cut-out: 150.797,36.1 150.797,28.3 145.337,28.3 145.3,28.263 145.3,36.1
  text "Inner Layer3 (Power/GND Plane)" at 55.2,92.1 h1.8
Bottom Layer:
  rectangle net SHIELD: 14,53.8 16.6,56.8
  rectangle net +24V_IN: 18.5,7.2 20.5,15.3
  rectangle net GND: 40.5,38.1 44.2,41.8
  rectangle net SHIELD: 30.35,0.4 35.35,2
  rectangle net +VPSE: 47.8,15.454 49.8,18.9
  rectangle net +VPSE: 75.7,29.8 78.8,32.05
  rectangle net +VPSE: 69.2,29.8 72.3,32.05
  rectangle net +VPSE: 62.7,29.8 65.8,32.05
  rectangle net +VPSE: 56.2,29.8 59.3,32.05
  rectangle net +VPSE: 49.7,29.8 52.8,32.05
  region net NetL1_3: 35.6,40.35 33.1,40.35 33.1,33.05 35.6,33.05
  rectangle net NetL1_2: 33.1,42.25 35.6,49.55
  region net POWER/DATA_P: 5.9,33.3 5.9,25.8 8.2,25.8 8.2,33.3
  region net POWER/DATA_N: 17.4,33.2 17.4,25.7 19.7,25.7 19.7,33.2
  rectangle net +3V3: 56,60.8 57.6,65.1
  rectangle net GND: 109.101,26.272 110.7,27.621
  pour cut-out: 111,6.3 111,9.9 111.118,10.018 112.882,10.018 113,9.9 113,6.3 112.9,6.2 111.1,6.2
  pour cut-out: 92.2,11.934 92.2,14.64 92.26,14.7 93.54,14.7 93.6,14.64 93.6,11.939 93.561,11.9 92.234,11.9
  pour cut-out: 82.8,8.7 83.382,9.282 83.382,29.006 82.744,29.644 77.344,29.644 71.1,23.4 71.1,16.334 71.9,15.534 71.9,5.3 71.5,4.9 53.2,4.9 52.7,4.4 52.7,3 52.4,2.7 52.8,2.7 53.313,2.7 53.327,2.714 53.327,3.875 53.638,4.187 72.419,4.187 72.792,4.561 72.792,15.514 76.411,19.132 76.411,26.761 76.935,27.285 80,27.285 80.075,27.21 80.075,2.7 81.3,2.7 80.9,3.1 80.9,8.408 81.192,8.7
  pour cut-out: 50.119,34.744 50.119,34.308 50.246,34.181 57.925,34.181 58.019,34.275 58.019,36.4 58.303,36.684 66.938,36.684 67.3,37.046 67.3,52.1 67.05,52.35 50.35,52.35 50.133,52.133 50.119,52.119 50.119,50.2 50.519,50.6 50.6,50.6 54.528,50.6 54.528,45.584 53.406,44.461 53.406,34.75 53.089,34.433 50.431,34.433
  region: 4.8,64
  pour cut-out: 149.7,36.1 149.7,28.3 145.337,28.3 145.3,28.263 145.3,36.1
  text "Bottom Layer" at 83.4,91.8 h1.8

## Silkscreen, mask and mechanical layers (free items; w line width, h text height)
Top Overlay:
  text "RESET" at 89.9,84 h0.76
  text "P0" at 84.9,73.7 h0.89
  text "MODE3" at 83.8,72.2 h0.76
  text "MEDIA_CNV" at 63.1,71.794 h0.76 r90
  text "MACIF_SEL1" at 65.64,71.794 h0.76 r90
  text "SWPD_N" at 68.16,71.794 h0.76 r90
  text "MACIF_SEL0" at 70.7,71.794 h0.76 r90
  text "TX2P4_DIS" at 73.24,71.794 h0.76 r90
  text "MS_SEL" at 75.76,71.794 h0.76 r90
  text "PHYAD_0" at 78.3,71.794 h0.76 r90
  text "PHYAD_1" at 80.84,71.794 h0.76 r90
  text "MODE2" at 83.8,70.5 h0.76
  text "MODE1" at 83.8,68.7 h0.76
  text "MODE0" at 83.8,66.9 h0.76
  text "SPEED" at 83.8,65.044 h0.76
  text "DUPLEX" at 83,63.2 h0.76
  text "SHD" at 10.1,62.52 h1
  text "P1" at 84.9,60 h0.89
  text "D_P" at 10.2,59 h1
  text "MODE3" at 83.8,58.5 h0.76
  text "MODE2" at 83.8,56.8 h0.76
  text "D_N" at 10.1,55.45 h1
  text "MODE1" at 83.8,55 h0.76
  text "NRST" at 69.4,54.3 h0.76
  text "MODE0" at 83.8,53.2 h0.76
  text "LINK" at 119.1,52.8 h0.76
  text "SPEED" at 123.5,52.8 h0.76
  text "3V3" at 135.65,51.57 h0.76 r90
  text "WP" at 138.19,51.57 h0.76 r90
  text "SCL" at 140.73,51.57 h0.76 r90
  text "SDA" at 143.27,51.57 h0.76 r90
  text "/ACT" at 118.8,51.5 h0.76
  text "SPEED" at 83.8,51.344 h0.76
  text "INT" at 50.4,51.2 h0.76 r90
  text "MDC" at 55.6,51 h0.76 r90
  text "MDIO" at 53,50.4 h0.76 r90
  text "DUPLEX" at 83,49.5 h0.76
  text "V+" at 44.8,48.2 h0.76
  text "1" at 133.158,46.65 h0.76
  text "GND" at 88.2,44.6 h0.76
  text "A0" at 135.62,44.1 h0.76 r90
  text "A1" at 138.16,44.1 h0.76 r90
  text "A2" at 140.7,44.1 h0.76 r90
  text "GND" at 143.2,43.3 h0.76 r90
  text "RX" at 88.2,42.1 h0.76
  text "SW" at 65.1,42 h0.76 r90
  text "EEPROM" at 133.922,42 h1
  text "Programming" at 134,40.2 h1
  text "TX" at 88.2,39.5 h0.76
  text "USER" at 63.6,39.2 h0.76 r90
  text "V-" at 44.85,38.3 h0.76
  text "LED" at 81.4,38.3 h0.64
  text "LED" at 65.1,37.226 h0.76 r90
  text "SWO" at 88.1,35 h0.76
  text "RST" at 88.2,32.39 h0.76
  text "DIO" at 88.2,30.04 h0.76
  text "GND" at 87.997,27.297 h0.76
  text "CLK" at 88.2,24.96 h0.76
  text "PRTPWR0" at 42.4,23.775 h0.76 r90
  text "3V3" at 88.2,22.42 h0.76
  text "VPSE" at 87.436,15.815 h0.76
  text "GND" at 117.243,13.3 h0.76
  text "+" at 18.5,8.8 h1.5
  text "-" at 24.6,8.8 h1.5
  text "3V3" at 117.4,7.7 h0.76
  text "+24V" at 27.9,4.4 h1
  text "Input" at 27.8,2.1 h1
Bottom Overlay:
  lines w0.178: 50.6,42.5 50.6,33.7 66.8,33.7 66.8,42.5 ; 50.6,42.5 50.6,51.9 66.8,51.9 66.8,42.5 ; 50.6,42.5 66.8,42.5
  text "SCCP" at 49.1,45.8 h0.76 r270
  text "SNUBBER" at 49.1,35.4 h0.76 r270
  text "PoDL - PSE V1.6" at 142,19.2 h3
  text "Pr.No.: 749949" at 142,16.2 h3
  text "Würth Elektronik eiSos" at 142,13.2 h2.2
  text "Max - Eyth - Str. 1" at 142,10.5 h2.2
  text "74638 Waldenburg" at 142,7.8 h2.2
  text "Germany" at 142,5.1 h2.2
Mechanical 1:
  drawing of 295 lines, arcs and shapes, not listed
  text "Layer" at 174.543,15.106 h1.52
  text "Name" at 184.955,15.106 h1.52
  text "Material" at 208.824,15.106 h1.52
  text "Thickness" at 230.662,15.106 h1.52
  text "Constant" at 247.168,15.106 h1.52
  text "Board Layer Stack" at 261.642,15.106 h1.52
  text "1" at 174.543,12.058 h1.52
  text "Top Overlay" at 184.955,12.058 h1.52
  text "2" at 174.543,9.01 h1.52
  text "Top Solder" at 184.955,9.01 h1.52
  text "Solder Resist" at 208.824,9.01 h1.52
  text "0.010mm" at 230.662,9.01 h1.52
  text "3.8" at 247.168,9.01 h1.52
  text "3" at 174.543,5.962 h1.52
  text "Top Layer" at 184.955,5.962 h1.52
  text "Copper" at 208.824,5.962 h1.52
  text "0.035mm" at 230.662,5.962 h1.52
  text "4" at 174.543,2.914 h1.52
  text "Dielectric 1" at 184.955,2.914 h1.52
  text "7628" at 208.824,2.914 h1.52
  text "0.210mm" at 230.662,2.914 h1.52
  text "4.6" at 247.168,2.914 h1.52
  text "5" at 174.543,-0.134 h1.52
  text "Signal Layer 2" at 184.955,-0.134 h1.52
  text "Copper" at 208.824,-0.134 h1.52
  text "0.015mm" at 230.662,-0.134 h1.52
  text "6" at 174.543,-3.182 h1.52
  text "Dielectric 3" at 184.955,-3.182 h1.52
  text "Core-009" at 208.824,-3.182 h1.52
  text "1.065mm" at 230.662,-3.182 h1.52
  text "4.6" at 247.168,-3.182 h1.52
  text "7" at 174.543,-6.23 h1.52
  text "Signal Layer 3" at 184.955,-6.23 h1.52
  text "Copper" at 208.824,-6.23 h1.52
  text "0.015mm" at 230.662,-6.23 h1.52
  text "8" at 174.543,-9.278 h1.52
  text "Dielectric 2" at 184.955,-9.278 h1.52
  text "PP-006" at 208.824,-9.278 h1.52
  text "0.210mm" at 230.662,-9.278 h1.52
  text "4.6" at 247.168,-9.278 h1.52
  text "9" at 174.543,-12.326 h1.52
  text "Bottom Layer" at 184.955,-12.326 h1.52
  text "Copper" at 208.824,-12.326 h1.52
  text "0.035mm" at 230.662,-12.326 h1.52
  text "10" at 174.543,-15.374 h1.52
  text "Bottom Solder" at 184.955,-15.374 h1.52
  text "Solder Resist" at 208.824,-15.374 h1.52
  text "0.010mm" at 230.662,-15.374 h1.52
  text "3.8" at 247.168,-15.374 h1.52
  text "11" at 174.543,-18.422 h1.52
  text "Bottom Overlay" at 184.955,-18.422 h1.52
Drill Drawing:
  drawing of 181 lines, arcs and shapes, not listed
  text "Symbol" at 175.415,90.98 h1.83
  text "Count" at 188.264,90.98 h1.83
  text "Hole Size" at 203.5,90.98 h1.83
  text "Plated" at 232.701,90.98 h1.83
  text "Hole Type" at 245.551,90.98 h1.83
  text "Drill Layer Pair" at 264.189,90.98 h1.83
  text "Via/Pad" at 302.278,90.98 h1.83
  text "Pad Shape" at 317.26,90.98 h1.83
  text "2" at 188.264,87.17 h1.52
  text "1.300mm (51.18mil)" at 203.5,87.17 h1.52
  text "PTH" at 232.701,87.17 h1.52
  text "Round" at 245.551,87.17 h1.52
  text "Top Layer - Bottom Layer" at 264.189,87.17 h1.52
  text "Pad" at 302.278,87.17 h1.52
  text "(Mixed)" at 317.26,87.17 h1.52
  text "2" at 188.264,83.36 h1.52
  text "1.600mm (62.99mil)" at 203.5,83.36 h1.52
  text "PTH" at 232.701,83.36 h1.52
  text "Round" at 245.551,83.36 h1.52
  text "Top Layer - Bottom Layer" at 264.189,83.36 h1.52
  text "Pad" at 302.278,83.36 h1.52
  text "Rounded" at 317.26,83.36 h1.52
  text "2" at 188.264,79.55 h1.52
  text "3.250mm (127.95mil)" at 203.5,79.55 h1.52
  text "NPTH" at 232.701,79.55 h1.52
  text "Round" at 245.551,79.55 h1.52
  text "Top Layer - Bottom Layer" at 264.189,79.55 h1.52
  text "Pad" at 302.278,79.55 h1.52
  text "Rounded" at 317.26,79.55 h1.52
  text "3" at 188.264,75.74 h1.52
  text "1.400mm (55.12mil)" at 203.5,75.74 h1.52
  text "PTH" at 232.701,75.74 h1.52
  text "Round" at 245.551,75.74 h1.52
  text "Top Layer - Bottom Layer" at 264.189,75.74 h1.52
  text "Pad" at 302.278,75.74 h1.52
  text "Rounded" at 317.26,75.74 h1.52
  text "B" at 174.676,75.486 h1.69
  text "4" at 188.264,71.93 h1.52
  text "0.381mm (15.00mil)" at 203.5,71.93 h1.52
  text "PTH" at 232.701,71.93 h1.52
  text "Round" at 245.551,71.93 h1.52
  text "Top Layer - Bottom Layer" at 264.189,71.93 h1.52
  text "Via" at 302.278,71.93 h1.52
  text "Rounded" at 317.26,71.93 h1.52
  text "4" at 188.264,68.12 h1.52
  text "0.600mm (23.62mil)" at 203.5,68.12 h1.52
  text "PTH" at 232.701,68.12 h1.52
  text "Slot" at 245.551,68.12 h1.52
  text "Top Layer - Bottom Layer" at 264.189,68.12 h1.52
  text "Pad" at 302.278,68.12 h1.52
  text "Rounded" at 317.26,68.12 h1.52
  text "4" at 188.264,64.31 h1.52
  text "1.000mm (39.37mil)" at 203.5,64.31 h1.52
  text "PTH" at 232.701,64.31 h1.52
  text "Round" at 245.551,64.31 h1.52
  text "Top Layer - Bottom Layer" at 264.189,64.31 h1.52
  text "Pad" at 302.278,64.31 h1.52
  text "Rounded" at 317.26,64.31 h1.52
  text "4" at 188.264,60.5 h1.52
  text "1.020mm (40.16mil)" at 203.5,60.5 h1.52
  text "PTH" at 232.701,60.5 h1.52
  text "Round" at 245.551,60.5 h1.52
  text "Top Layer - Bottom Layer" at 264.189,60.5 h1.52
  text "Pad" at 302.278,60.5 h1.52
  text "Rounded" at 317.26,60.5 h1.52
  text "5" at 188.264,56.69 h1.52
  text "3.200mm (125.98mil)" at 203.5,56.69 h1.52
  text "PTH" at 232.701,56.69 h1.52
  text "Round" at 245.551,56.69 h1.52
  text "Top Layer - Bottom Layer" at 264.189,56.69 h1.52
  text "Pad" at 302.278,56.69 h1.52
  text "Rounded" at 317.26,56.69 h1.52
  text "8" at 188.264,52.88 h1.52
  text "0.457mm (18.00mil)" at 203.5,52.88 h1.52
  text "PTH" at 232.701,52.88 h1.52
  text "Round" at 245.551,52.88 h1.52
  text "Top Layer - Bottom Layer" at 264.189,52.88 h1.52
  text "Via" at 302.278,52.88 h1.52
  text "Rounded" at 317.26,52.88 h1.52
  text "14" at 188.264,49.07 h1.52
  text "0.400mm (15.75mil)" at 203.5,49.07 h1.52
  text "PTH" at 232.701,49.07 h1.52
  text "Round" at 245.551,49.07 h1.52
  text "Top Layer - Bottom Layer" at 264.189,49.07 h1.52
  text "Pad" at 302.278,49.07 h1.52
  text "Rounded" at 317.26,49.07 h1.52
  text "34" at 188.264,45.26 h1.52
  text "0.900mm (35.43mil)" at 203.5,45.26 h1.52
  text "PTH" at 232.701,45.26 h1.52
  text "Round" at 245.551,45.26 h1.52
  text "Top Layer - Bottom Layer" at 264.189,45.26 h1.52
  text "Pad" at 302.278,45.26 h1.52
  text "(Mixed)" at 317.26,45.26 h1.52
  text "40" at 188.264,41.45 h1.52
  text "0.508mm (20.00mil)" at 203.5,41.45 h1.52
  text "PTH" at 232.701,41.45 h1.52
  text "Round" at 245.551,41.45 h1.52
  text "Top Layer - Bottom Layer" at 264.189,41.45 h1.52
  text "Via" at 302.278,41.45 h1.52
  text "Rounded" at 317.26,41.45 h1.52
  text "173" at 188.264,37.64 h1.52
  text "0.200mm (7.87mil)" at 203.5,37.64 h1.52
  text "PTH" at 232.701,37.64 h1.52
  text "Round" at 245.551,37.64 h1.52
  text "Top Layer - Bottom Layer" at 264.189,37.64 h1.52
  text "Via" at 302.278,37.64 h1.52
  text "Rounded" at 317.26,37.64 h1.52
  text "639" at 188.264,33.83 h1.52
  text "0.300mm (11.81mil)" at 203.5,33.83 h1.52
  text "PTH" at 232.701,33.83 h1.52
  text "Round" at 245.551,33.83 h1.52
  text "Top Layer - Bottom Layer" at 264.189,33.83 h1.52
  text "Via" at 302.278,33.83 h1.52
  text "Rounded" at 317.26,33.83 h1.52
  text "938 Total" at 188.264,30.02 h1.52
  text "Slot definitions :" at 175.415,26.338 h1.52
  text "Routed Path Length" at 201.645,26.338 h1.52
  text "= Calculated from tool start centre position to tool end centre position." at 229.653,26.338 h1.52
  text "Hole Length" at 201.645,23.798 h1.52
  text "= Routed Path Length + Tool Size = Slot length as defined in the PCB layout" at 219.242,23.798 h1.52

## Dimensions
0,86.5 to 0,0 on Mechanical 1
0,0 to 155,0 on Mechanical 1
